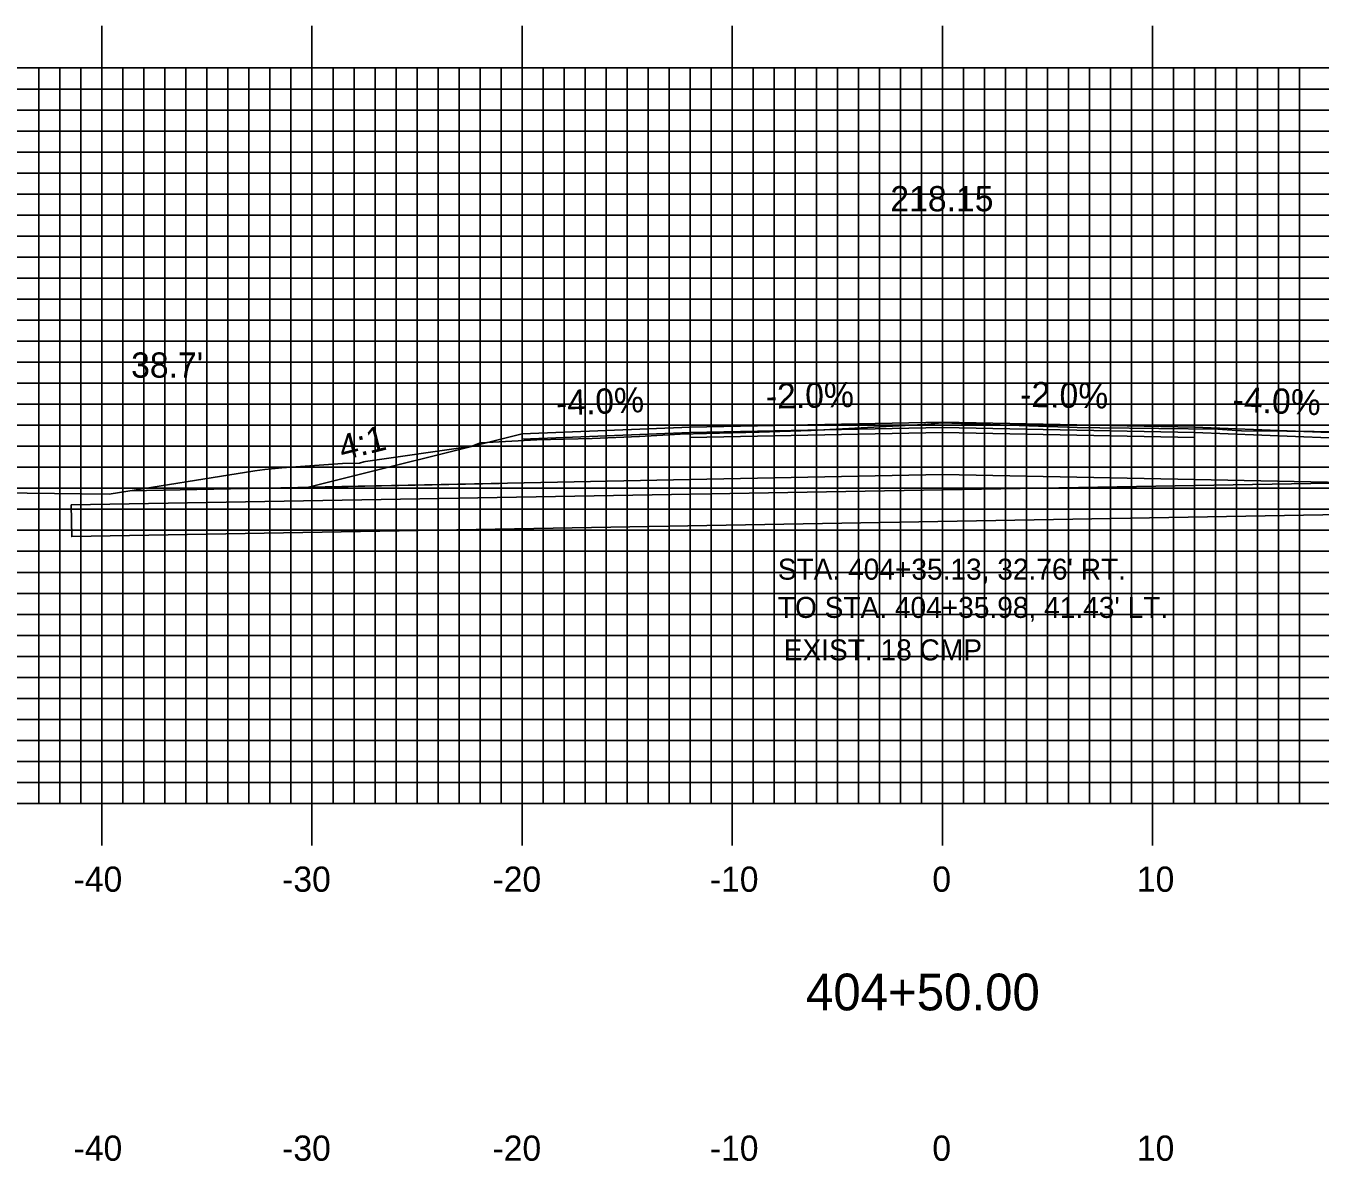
# Model space of a CAD drawing. Extents: x 851348 to 851692, y 364785 to 365005.
# Drawn here: x 851470.6 to 851532.2, y 364841.2 to 364895.2 of the extents above; entities that cross this region are included whole.
import ezdxf

# ---------------------------------------------------------------- set-up
doc = ezdxf.new("R2010")
doc.units = 0
for name, color, linetype in [('ANNOTATION', 7, 'Continuous'), ('D_Drainage_Culvert', 7, 'Continuous'), ('D_Roadway_Centerline', 7, 'Continuous'), ('D_Roadway_Centerline_Text', 7, 'Continuous'), ('D_Roadway_Edge_Shoulder', 7, 'Continuous'), ('D_Roadway_Edge_TW', 7, 'Continuous'), ('D_Roadway_Pavement', 7, 'Continuous'), ('D_Roadway_SubGrade', 7, 'Continuous'), ('D_Text_Monospaced', 7, 'Continuous'), ('D_Text_Standard', 7, 'Continuous'), ('H_V ANNOTATION', 7, 'Continuous'), ('MAJOR', 7, 'Continuous'), ('MINOR', 7, 'Continuous'), ('S_Roadway_Centerline', 7, 'Continuous')]:
    doc.layers.add(name, color=color, linetype=linetype)

msp = doc.modelspace()

# ---------------------------------------------------------------- linework, layer by layer
at = {"layer": 'ANNOTATION'}
msp.add_line((851493.104, 364873.462), (851475.518, 364873.11), dxfattribs=at)
at = {"layer": 'D_Drainage_Culvert'}
msp.add_line((851472.732, 364872.438), (851546.926, 364873.729), dxfattribs=at)
msp.add_lwpolyline([(851472.732, 364872.438), (851472.758, 364870.938), (851546.952, 364872.229), (851546.926, 364873.729)], dxfattribs=at)
at = {"layer": 'D_Roadway_Centerline'}
msp.add_lwpolyline([(851484.018, 364873.28), (851494.191, 364875.823), (851502.191, 364876.143), (851514.191, 364876.383), (851526.191, 364876.143), (851534.191, 364875.823), (851544.365, 364873.28), (851548.365, 364872.28), (851557.607, 364876.901), (851558.857, 364877.48), (851560.107, 364877.969), (851561.357, 364878.366), (851562.607, 364878.671)], dxfattribs=at)
at = {"layer": 'D_Roadway_Edge_Shoulder'}
for points in [[(851502.191, 364876.143), (851494.191, 364875.823), (851494.191, 364875.573), (851502.191, 364875.893)], [(851526.191, 364876.143), (851534.191, 364875.823), (851534.191, 364875.573), (851526.191, 364875.893)]]:
    msp.add_lwpolyline(points, close=True, dxfattribs=at)
at = {"layer": 'D_Roadway_Edge_TW'}
msp.add_lwpolyline([(851502.191, 364875.893), (851502.191, 364876.143), (851514.191, 364876.383), (851526.191, 364876.143), (851526.191, 364875.893), (851514.191, 364876.133)], close=True, dxfattribs=at)
at = {"layer": 'D_Roadway_Pavement'}
msp.add_lwpolyline([(851502.191, 364875.643), (851502.191, 364875.893), (851514.191, 364876.133), (851526.191, 364875.893), (851526.191, 364875.643), (851514.191, 364875.883)], close=True, dxfattribs=at)
at = {"layer": 'D_Roadway_SubGrade'}
msp.add_lwpolyline([(851502.191, 364873.643), (851484.018, 364873.28), (851494.191, 364875.823), (851494.191, 364875.573), (851502.191, 364875.893), (851514.191, 364876.133), (851526.191, 364875.893), (851534.191, 364875.573), (851534.191, 364875.823), (851544.365, 364873.28), (851526.191, 364873.643), (851514.191, 364873.883)], close=True, dxfattribs=at)
at = {"layer": 'MAJOR'}
for p, q in [((851474.191, 364895.237), (851474.191, 364893.233)), ((851484.191, 364895.237), (851484.191, 364893.233)), ((851494.191, 364895.237), (851494.191, 364893.233)), ((851504.191, 364895.237), (851504.191, 364893.233)), ((851514.191, 364895.237), (851514.191, 364893.233)), ((851524.191, 364895.237), (851524.191, 364893.233)), ((851374.191, 364893.233), (851654.191, 364893.233)), ((851374.191, 364893.233), (851654.191, 364893.233)), ((851474.191, 364858.233), (851474.191, 364893.233)), ((851484.191, 364858.233), (851484.191, 364893.233)), ((851494.191, 364858.233), (851494.191, 364893.233)), ((851504.191, 364858.233), (851504.191, 364893.233)), ((851514.191, 364858.233), (851514.191, 364893.233)), ((851524.191, 364858.233), (851524.191, 364893.233)), ((851374.191, 364888.233), (851654.191, 364888.233)), ((851374.191, 364883.233), (851654.191, 364883.233)), ((851374.191, 364878.233), (851654.191, 364878.233)), ((851374.191, 364873.233), (851654.191, 364873.233)), ((851374.191, 364868.233), (851654.191, 364868.233)), ((851374.191, 364863.233), (851654.191, 364863.233)), ((851374.191, 364858.233), (851654.191, 364858.233)), ((851374.191, 364858.233), (851654.191, 364858.233)), ((851474.191, 364856.229), (851474.191, 364858.233)), ((851484.191, 364856.229), (851484.191, 364858.233)), ((851494.191, 364856.229), (851494.191, 364858.233)), ((851504.191, 364856.229), (851504.191, 364858.233)), ((851514.191, 364856.229), (851514.191, 364858.233)), ((851524.191, 364856.229), (851524.191, 364858.233))]:
    msp.add_line(p, q, dxfattribs=at)
at = {"layer": 'MINOR'}
for p, q in [((851471.191, 364858.233), (851471.191, 364893.233)), ((851472.191, 364858.233), (851472.191, 364893.233)), ((851473.191, 364858.233), (851473.191, 364893.233)), ((851475.191, 364858.233), (851475.191, 364893.233)), ((851476.191, 364858.233), (851476.191, 364893.233)), ((851477.191, 364858.233), (851477.191, 364893.233)), ((851478.191, 364858.233), (851478.191, 364893.233)), ((851479.191, 364858.233), (851479.191, 364893.233)), ((851480.191, 364858.233), (851480.191, 364893.233)), ((851481.191, 364858.233), (851481.191, 364893.233)), ((851482.191, 364858.233), (851482.191, 364893.233)), ((851483.191, 364858.233), (851483.191, 364893.233)), ((851485.191, 364858.233), (851485.191, 364893.233)), ((851486.191, 364858.233), (851486.191, 364893.233)), ((851487.191, 364858.233), (851487.191, 364893.233)), ((851488.191, 364858.233), (851488.191, 364893.233)), ((851489.191, 364858.233), (851489.191, 364893.233)), ((851490.191, 364858.233), (851490.191, 364893.233)), ((851491.191, 364858.233), (851491.191, 364893.233)), ((851492.191, 364858.233), (851492.191, 364893.233)), ((851493.191, 364858.233), (851493.191, 364893.233)), ((851495.191, 364858.233), (851495.191, 364893.233)), ((851496.191, 364858.233), (851496.191, 364893.233)), ((851497.191, 364858.233), (851497.191, 364893.233)), ((851498.191, 364858.233), (851498.191, 364893.233)), ((851499.191, 364858.233), (851499.191, 364893.233)), ((851500.191, 364858.233), (851500.191, 364893.233)), ((851501.191, 364858.233), (851501.191, 364893.233)), ((851502.191, 364858.233), (851502.191, 364893.233)), ((851503.191, 364858.233), (851503.191, 364893.233)), ((851505.191, 364858.233), (851505.191, 364893.233)), ((851506.191, 364858.233), (851506.191, 364893.233)), ((851507.191, 364858.233), (851507.191, 364893.233)), ((851508.191, 364858.233), (851508.191, 364893.233)), ((851509.191, 364858.233), (851509.191, 364893.233)), ((851510.191, 364858.233), (851510.191, 364893.233)), ((851511.191, 364858.233), (851511.191, 364893.233)), ((851512.191, 364858.233), (851512.191, 364893.233)), ((851513.191, 364858.233), (851513.191, 364893.233)), ((851515.191, 364858.233), (851515.191, 364893.233)), ((851516.191, 364858.233), (851516.191, 364893.233)), ((851517.191, 364858.233), (851517.191, 364893.233)), ((851518.191, 364858.233), (851518.191, 364893.233)), ((851519.191, 364858.233), (851519.191, 364893.233)), ((851520.191, 364858.233), (851520.191, 364893.233)), ((851521.191, 364858.233), (851521.191, 364893.233)), ((851522.191, 364858.233), (851522.191, 364893.233)), ((851523.191, 364858.233), (851523.191, 364893.233)), ((851525.191, 364858.233), (851525.191, 364893.233)), ((851526.191, 364858.233), (851526.191, 364893.233)), ((851527.191, 364858.233), (851527.191, 364893.233)), ((851528.191, 364858.233), (851528.191, 364893.233)), ((851529.191, 364858.233), (851529.191, 364893.233)), ((851530.191, 364858.233), (851530.191, 364893.233)), ((851531.191, 364858.233), (851531.191, 364893.233)), ((851374.191, 364892.233), (851654.191, 364892.233)), ((851374.191, 364891.233), (851654.191, 364891.233)), ((851374.191, 364890.233), (851654.191, 364890.233)), ((851374.191, 364889.233), (851654.191, 364889.233)), ((851374.191, 364887.233), (851654.191, 364887.233)), ((851374.191, 364886.233), (851654.191, 364886.233)), ((851374.191, 364885.233), (851654.191, 364885.233)), ((851374.191, 364884.233), (851654.191, 364884.233)), ((851374.191, 364882.233), (851654.191, 364882.233)), ((851374.191, 364881.233), (851654.191, 364881.233)), ((851374.191, 364880.233), (851654.191, 364880.233)), ((851374.191, 364879.233), (851654.191, 364879.233)), ((851374.191, 364877.233), (851654.191, 364877.233)), ((851374.191, 364876.233), (851654.191, 364876.233)), ((851374.191, 364875.233), (851654.191, 364875.233)), ((851374.191, 364874.233), (851654.191, 364874.233)), ((851374.191, 364872.233), (851654.191, 364872.233)), ((851374.191, 364871.233), (851654.191, 364871.233)), ((851374.191, 364870.233), (851654.191, 364870.233)), ((851374.191, 364869.233), (851654.191, 364869.233)), ((851374.191, 364867.233), (851654.191, 364867.233)), ((851374.191, 364866.233), (851654.191, 364866.233)), ((851374.191, 364865.233), (851654.191, 364865.233)), ((851374.191, 364864.233), (851654.191, 364864.233)), ((851374.191, 364862.233), (851654.191, 364862.233)), ((851374.191, 364861.233), (851654.191, 364861.233)), ((851374.191, 364860.233), (851654.191, 364860.233)), ((851374.191, 364859.233), (851654.191, 364859.233))]:
    msp.add_line(p, q, dxfattribs=at)
at = {"layer": 'S_Roadway_Centerline'}
msp.add_lwpolyline([(851465.181, 364873.111), (851470.639, 364873.007), (851474.535, 364872.953), (851481.478, 364874.063), (851481.941, 364874.122), (851482.763, 364874.206), (851485.635, 364874.409), (851486.445, 364874.434), (851486.651, 364874.499), (851486.735, 364874.506), (851491.611, 364875.209), (851491.72, 364875.234), (851491.846, 364875.247), (851492.205, 364875.4), (851494.891, 364875.534), (851497.528, 364875.604), (851499.774, 364875.693), (851501.713, 364875.814), (851505.47, 364875.899), (851507.942, 364875.988), (851513.304, 364876.273), (851514.185, 364876.349), (851520.602, 364876.125), (851521.674, 364876.103), (851527.289, 364876.045), (851527.512, 364876.023), (851528.428, 364875.97), (851530.584, 364875.954), (851534.474, 364875.898)], dxfattribs=at)

# ---------------------------------------------------------------- texts
at = {"layer": 'ANNOTATION'}
for s, rotation, p in [('-4.0%', 2.29061, (851495.823, 364876.69)), ('-2.0%', 1.14576, (851505.798, 364877.016)), ('-2.0%', 358.85424, (851517.878, 364877.11)), ('-4.0%', 357.70939, (851527.983, 364876.873)), ('4:1', 14.03624, (851485.64, 364874.547))]:
    msp.add_text(s, height=1.2, rotation=rotation, dxfattribs=at).set_placement(p)
at = {"layer": 'D_Roadway_Centerline'}
for s, p in [('C', (851514.186, 364876.383)), ('L', (851514.191, 364876.376))]:
    msp.add_text(s, height=0.0146, dxfattribs=at).set_placement(p)
at = {"layer": 'D_Roadway_Centerline_Text'}
msp.add_text('218.15', height=1.2, dxfattribs=at).set_placement((851511.714, 364886.413))
at = {"layer": 'D_Text_Monospaced'}
for s, p in [("STA. 404+35.13, 32.76' RT.", (851506.357, 364868.883)), ("TO STA. 404+35.98, 41.43' LT.", (851506.357, 364867.064)), ('EXIST. 18 CMP', (851506.639, 364865.043))]:
    msp.add_text(s, height=0.99996, dxfattribs=at).set_placement(p)
at = {"layer": 'D_Text_Standard'}
msp.add_text("38.7'", height=1.2, dxfattribs=at).set_placement((851475.583, 364878.497))
at = {"layer": 'H_V ANNOTATION'}
for s, height, p in [('-40', 1.2, (851472.843, 364854.033)), ('-30', 1.2, (851482.768, 364854.033)), ('-20', 1.2, (851492.778, 364854.033)), ('-10', 1.2, (851503.121, 364854.033)), ('0', 1.2, (851513.71, 364854.033)), ('10', 1.2, (851523.442, 364854.033)), ('404+50.00', 1.75, (851507.699, 364848.389)), ('-40', 1.2, (851472.843, 364841.233)), ('-30', 1.2, (851482.768, 364841.233)), ('-20', 1.2, (851492.778, 364841.233)), ('-10', 1.2, (851503.121, 364841.233)), ('0', 1.2, (851513.71, 364841.233)), ('10', 1.2, (851523.442, 364841.233))]:
    msp.add_text(s, height=height, dxfattribs=at).set_placement(p)
at = {"layer": 'S_Roadway_Centerline'}
for s, p in [('L', (851514.176, 364876.342)), ('C', (851514.18, 364876.349))]:
    msp.add_text(s, height=0.0146, dxfattribs=at).set_placement(p)

doc.saveas('drawing.dxf')
